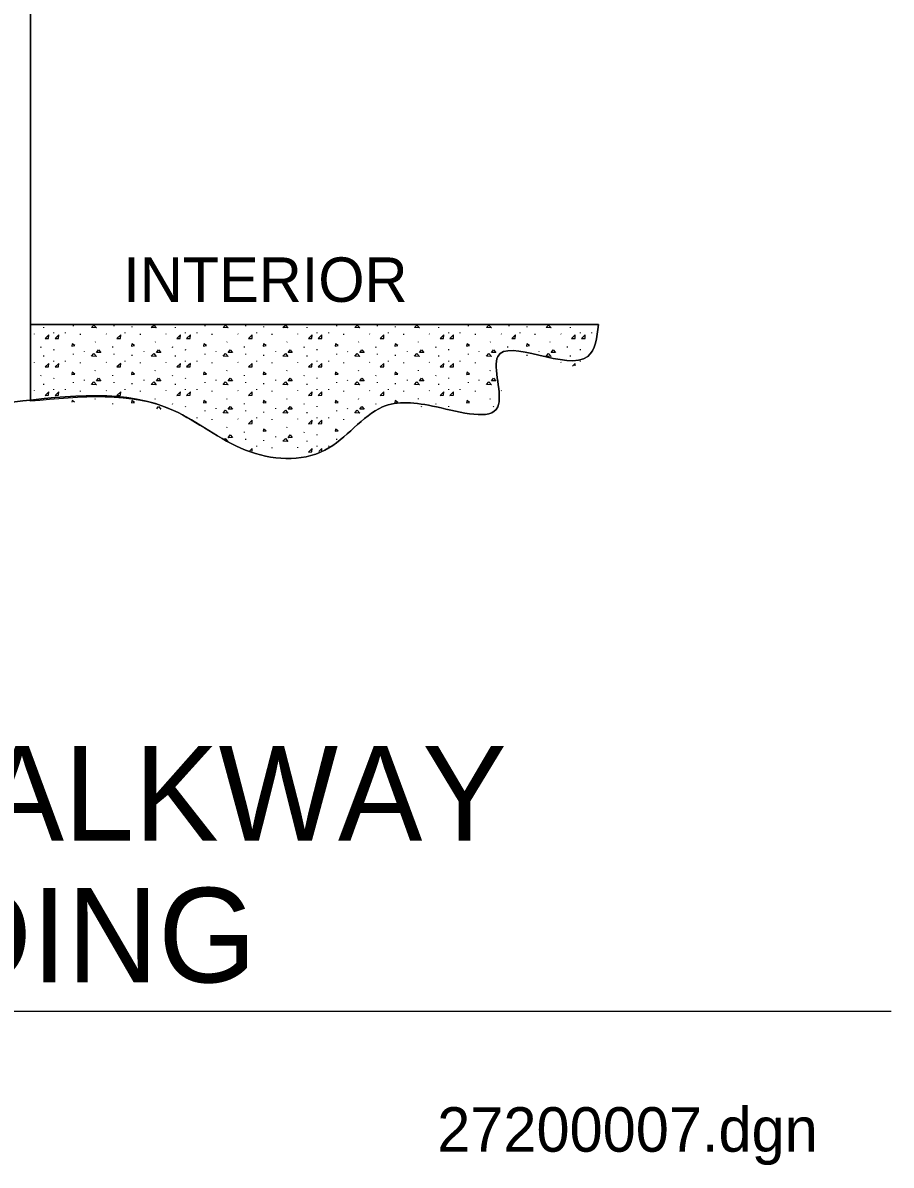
# Model space of a CAD drawing. Extents: x 10099.2 to 10148.4, y 10073.3 to 10116.7.
# Drawn here: x 10135.41 to 10148.42, y 10073.35 to 10090.47 of the extents above; entities that cross this region are included whole.
import ezdxf

# ---------------------------------------------------------------- set-up
doc = ezdxf.new("R2010")
doc.units = 0
for name, color, linetype in [('Level 52', 7, 'Continuous'), ('Level 60', 7, 'Continuous'), ('Level 61', 7, 'Continuous'), ('Level 63', 7, 'Continuous')]:
    doc.layers.add(name, color=color, linetype=linetype)

msp = doc.modelspace()

# ---------------------------------------------------------------- linework, layer by layer
at = {"layer": 'Level 52'}
msp.add_line((10099.233, 10075.654), (10148.423, 10075.654), dxfattribs=at)
at = {"layer": 'Level 60'}
for p, q in [((10144.04, 10085.947), (10135.528, 10085.947)), ((10135.528, 10085.947), (10144.04, 10085.947)), ((10135.528, 10085.947), (10144.04, 10085.947)), ((10135.591, 10085.8), (10135.588, 10085.808)), ((10135.729, 10085.894), (10135.729, 10085.906)), ((10135.879, 10085.818), (10135.879, 10085.828)), ((10136.052, 10085.818), (10136.052, 10085.828)), ((10136.175, 10085.921), (10136.175, 10085.932)), ((10136.28, 10085.792), (10136.28, 10085.804)), ((10136.667, 10085.8), (10136.664, 10085.808)), ((10136.782, 10085.921), (10136.782, 10085.932)), ((10136.949, 10085.818), (10136.949, 10085.828)), ((10137.052, 10085.904), (10137.052, 10085.915)), ((10137.176, 10085.792), (10137.176, 10085.804)), ((10137.563, 10085.8), (10137.56, 10085.808)), ((10137.701, 10085.894), (10137.701, 10085.906)), ((10137.851, 10085.818), (10137.851, 10085.828)), ((10138.024, 10085.818), (10138.024, 10085.828)), ((10138.147, 10085.921), (10138.147, 10085.932)), ((10138.252, 10085.792), (10138.252, 10085.804)), ((10138.639, 10085.8), (10138.636, 10085.808)), ((10138.754, 10085.921), (10138.754, 10085.932)), ((10138.921, 10085.818), (10138.921, 10085.828)), ((10139.024, 10085.904), (10139.024, 10085.915)), ((10139.148, 10085.792), (10139.148, 10085.804)), ((10139.535, 10085.8), (10139.532, 10085.808)), ((10139.673, 10085.894), (10139.673, 10085.906)), ((10139.823, 10085.818), (10139.823, 10085.828)), ((10139.996, 10085.818), (10139.996, 10085.828)), ((10140.119, 10085.921), (10140.119, 10085.932)), ((10140.224, 10085.792), (10140.224, 10085.804)), ((10140.611, 10085.8), (10140.608, 10085.808)), ((10140.726, 10085.921), (10140.726, 10085.932)), ((10140.893, 10085.818), (10140.893, 10085.828)), ((10140.996, 10085.904), (10140.996, 10085.915)), ((10141.12, 10085.792), (10141.12, 10085.804)), ((10141.507, 10085.8), (10141.504, 10085.808)), ((10141.645, 10085.894), (10141.645, 10085.906)), ((10141.795, 10085.818), (10141.795, 10085.828)), ((10141.968, 10085.818), (10141.968, 10085.828)), ((10142.091, 10085.921), (10142.091, 10085.932)), ((10142.196, 10085.792), (10142.196, 10085.804)), ((10142.583, 10085.8), (10142.58, 10085.808)), ((10142.698, 10085.921), (10142.698, 10085.932)), ((10142.865, 10085.818), (10142.865, 10085.828)), ((10142.968, 10085.904), (10142.968, 10085.915)), ((10143.092, 10085.792), (10143.092, 10085.804)), ((10143.479, 10085.8), (10143.476, 10085.808)), ((10143.617, 10085.894), (10143.617, 10085.906)), ((10143.767, 10085.818), (10143.767, 10085.828)), ((10143.94, 10085.818), (10143.94, 10085.828)), ((10135.686, 10085.603), (10135.688, 10085.614)), ((10136.5, 10085.679), (10136.504, 10085.688)), ((10136.761, 10085.603), (10136.764, 10085.614)), ((10137.396, 10085.679), (10137.4, 10085.688)), ((10137.658, 10085.603), (10137.66, 10085.614)), ((10138.472, 10085.679), (10138.476, 10085.688)), ((10138.733, 10085.603), (10138.736, 10085.614)), ((10139.368, 10085.679), (10139.372, 10085.688)), ((10139.63, 10085.603), (10139.632, 10085.614)), ((10140.444, 10085.679), (10140.448, 10085.688)), ((10140.705, 10085.603), (10140.708, 10085.614)), ((10141.34, 10085.679), (10141.344, 10085.688)), ((10141.602, 10085.603), (10141.604, 10085.614)), ((10142.416, 10085.679), (10142.42, 10085.688)), ((10142.678, 10085.603), (10142.68, 10085.614)), ((10143.312, 10085.679), (10143.316, 10085.688)), ((10143.574, 10085.603), (10143.576, 10085.614)), ((10135.729, 10085.469), (10135.729, 10085.481)), ((10135.879, 10085.563), (10135.882, 10085.575)), ((10136.175, 10085.496), (10136.175, 10085.507)), ((10136.336, 10085.534), (10136.337, 10085.543)), ((10136.782, 10085.496), (10136.782, 10085.507)), ((10137.052, 10085.479), (10137.052, 10085.49)), ((10137.233, 10085.534), (10137.233, 10085.543)), ((10137.701, 10085.469), (10137.701, 10085.481)), ((10137.851, 10085.563), (10137.854, 10085.575)), ((10138.147, 10085.496), (10138.147, 10085.507)), ((10138.308, 10085.534), (10138.309, 10085.543)), ((10138.754, 10085.496), (10138.754, 10085.507)), ((10139.024, 10085.479), (10139.024, 10085.49)), ((10139.205, 10085.534), (10139.205, 10085.543)), ((10139.673, 10085.469), (10139.673, 10085.481)), ((10139.823, 10085.563), (10139.826, 10085.575)), ((10140.119, 10085.496), (10140.119, 10085.507)), ((10140.28, 10085.534), (10140.281, 10085.543)), ((10140.726, 10085.496), (10140.726, 10085.507)), ((10140.996, 10085.479), (10140.996, 10085.49)), ((10141.177, 10085.534), (10141.177, 10085.543)), ((10141.645, 10085.469), (10141.645, 10085.481)), ((10141.795, 10085.563), (10141.798, 10085.575)), ((10142.091, 10085.496), (10142.091, 10085.507)), ((10142.252, 10085.534), (10142.253, 10085.543)), ((10142.968, 10085.479), (10142.968, 10085.49)), ((10143.149, 10085.534), (10143.149, 10085.543)), ((10143.617, 10085.469), (10143.617, 10085.481)), ((10143.767, 10085.563), (10143.77, 10085.575)), ((10135.591, 10085.375), (10135.588, 10085.383)), ((10135.879, 10085.392), (10135.879, 10085.402)), ((10136.052, 10085.392), (10136.052, 10085.402)), ((10136.28, 10085.367), (10136.28, 10085.378)), ((10136.5, 10085.254), (10136.504, 10085.263)), ((10136.667, 10085.375), (10136.664, 10085.383)), ((10136.949, 10085.392), (10136.949, 10085.402)), ((10137.176, 10085.367), (10137.176, 10085.378)), ((10137.396, 10085.254), (10137.4, 10085.263)), ((10137.563, 10085.375), (10137.56, 10085.383)), ((10137.851, 10085.392), (10137.851, 10085.402)), ((10138.024, 10085.392), (10138.024, 10085.402)), ((10138.252, 10085.367), (10138.252, 10085.378)), ((10138.472, 10085.254), (10138.476, 10085.263)), ((10138.639, 10085.375), (10138.636, 10085.383)), ((10138.921, 10085.392), (10138.921, 10085.402)), ((10139.148, 10085.367), (10139.148, 10085.378)), ((10139.368, 10085.254), (10139.372, 10085.263)), ((10139.535, 10085.375), (10139.532, 10085.383)), ((10139.823, 10085.392), (10139.823, 10085.402)), ((10139.996, 10085.392), (10139.996, 10085.402)), ((10140.224, 10085.367), (10140.224, 10085.378)), ((10140.444, 10085.254), (10140.448, 10085.263)), ((10140.611, 10085.375), (10140.608, 10085.383)), ((10140.893, 10085.392), (10140.893, 10085.402)), ((10141.12, 10085.367), (10141.12, 10085.378)), ((10141.34, 10085.254), (10141.344, 10085.263)), ((10141.507, 10085.375), (10141.504, 10085.383)), ((10141.795, 10085.392), (10141.795, 10085.402)), ((10141.968, 10085.392), (10141.968, 10085.402)), ((10142.196, 10085.367), (10142.196, 10085.378)), ((10142.416, 10085.254), (10142.42, 10085.263)), ((10143.479, 10085.375), (10143.476, 10085.383)), ((10143.767, 10085.392), (10143.767, 10085.402)), ((10135.686, 10085.177), (10135.688, 10085.189)), ((10135.879, 10085.138), (10135.882, 10085.149)), ((10136.175, 10085.07), (10136.175, 10085.082)), ((10136.336, 10085.109), (10136.337, 10085.118)), ((10136.761, 10085.177), (10136.764, 10085.189)), ((10136.782, 10085.07), (10136.782, 10085.082)), ((10137.233, 10085.109), (10137.233, 10085.118)), ((10137.658, 10085.177), (10137.66, 10085.189)), ((10137.851, 10085.138), (10137.854, 10085.149)), ((10138.147, 10085.07), (10138.147, 10085.082)), ((10138.308, 10085.109), (10138.309, 10085.118)), ((10138.733, 10085.177), (10138.736, 10085.189)), ((10138.754, 10085.07), (10138.754, 10085.082)), ((10139.205, 10085.109), (10139.205, 10085.118)), ((10139.63, 10085.177), (10139.632, 10085.189)), ((10139.823, 10085.138), (10139.826, 10085.149)), ((10140.119, 10085.07), (10140.119, 10085.082)), ((10140.28, 10085.109), (10140.281, 10085.118)), ((10140.705, 10085.177), (10140.708, 10085.189)), ((10140.726, 10085.07), (10140.726, 10085.082)), ((10141.177, 10085.109), (10141.177, 10085.118)), ((10141.602, 10085.177), (10141.604, 10085.189)), ((10141.795, 10085.138), (10141.798, 10085.149)), ((10142.091, 10085.07), (10142.091, 10085.082)), ((10142.252, 10085.109), (10142.253, 10085.118)), ((10135.591, 10084.95), (10135.588, 10084.958)), ((10135.729, 10085.044), (10135.729, 10085.055)), ((10135.879, 10084.967), (10135.879, 10084.977)), ((10136.052, 10084.967), (10136.052, 10084.977)), ((10136.28, 10084.942), (10136.28, 10084.953)), ((10136.667, 10084.95), (10136.664, 10084.958)), ((10136.949, 10084.967), (10136.949, 10084.977)), ((10137.052, 10085.053), (10137.052, 10085.065)), ((10137.176, 10084.942), (10137.176, 10084.953)), ((10137.563, 10084.95), (10137.56, 10084.958)), ((10137.701, 10085.044), (10137.701, 10085.055)), ((10137.851, 10084.967), (10137.851, 10084.977)), ((10138.024, 10084.967), (10138.024, 10084.977)), ((10138.252, 10084.942), (10138.252, 10084.953)), ((10138.639, 10084.95), (10138.636, 10084.958)), ((10138.921, 10084.967), (10138.921, 10084.977)), ((10139.024, 10085.053), (10139.024, 10085.065)), ((10139.148, 10084.942), (10139.148, 10084.953)), ((10139.535, 10084.95), (10139.532, 10084.958)), ((10139.673, 10085.044), (10139.673, 10085.055)), ((10139.823, 10084.967), (10139.823, 10084.977)), ((10139.996, 10084.967), (10139.996, 10084.977)), ((10140.224, 10084.942), (10140.224, 10084.953)), ((10140.611, 10084.95), (10140.608, 10084.958)), ((10140.893, 10084.967), (10140.893, 10084.977)), ((10140.996, 10085.053), (10140.996, 10085.065)), ((10141.12, 10084.942), (10141.12, 10084.953)), ((10141.507, 10084.95), (10141.504, 10084.958)), ((10141.645, 10085.044), (10141.645, 10085.055)), ((10141.795, 10084.967), (10141.795, 10084.977)), ((10141.968, 10084.967), (10141.968, 10084.977)), ((10142.196, 10084.942), (10142.196, 10084.953)), ((10142.583, 10084.95), (10142.58, 10084.958)), ((10136.5, 10084.828), (10136.504, 10084.837)), ((10136.761, 10084.752), (10136.764, 10084.764)), ((10137.396, 10084.828), (10137.4, 10084.837)), ((10137.658, 10084.752), (10137.66, 10084.764)), ((10138.472, 10084.828), (10138.476, 10084.837)), ((10138.733, 10084.752), (10138.736, 10084.764)), ((10139.368, 10084.828), (10139.372, 10084.837)), ((10139.63, 10084.752), (10139.632, 10084.764)), ((10140.444, 10084.828), (10140.448, 10084.837)), ((10140.705, 10084.752), (10140.708, 10084.764)), ((10141.34, 10084.828), (10141.344, 10084.837)), ((10141.602, 10084.752), (10141.604, 10084.764)), ((10142.416, 10084.828), (10142.42, 10084.837)), ((10137.851, 10084.713), (10137.854, 10084.724)), ((10138.147, 10084.645), (10138.147, 10084.657)), ((10138.308, 10084.684), (10138.309, 10084.693)), ((10138.754, 10084.645), (10138.754, 10084.657)), ((10139.024, 10084.628), (10139.024, 10084.639)), ((10139.205, 10084.684), (10139.205, 10084.693)), ((10139.673, 10084.618), (10139.673, 10084.63)), ((10139.823, 10084.713), (10139.826, 10084.724)), ((10140.119, 10084.645), (10140.119, 10084.657)), ((10140.28, 10084.684), (10140.281, 10084.693)), ((10141.795, 10084.713), (10141.798, 10084.724)), ((10138.024, 10084.542), (10138.024, 10084.552)), ((10138.252, 10084.516), (10138.252, 10084.528)), ((10138.472, 10084.403), (10138.476, 10084.412)), ((10138.639, 10084.525), (10138.636, 10084.533)), ((10138.921, 10084.542), (10138.921, 10084.552)), ((10139.148, 10084.516), (10139.148, 10084.528)), ((10139.368, 10084.403), (10139.372, 10084.412)), ((10139.535, 10084.525), (10139.532, 10084.533)), ((10139.823, 10084.542), (10139.823, 10084.552)), ((10139.996, 10084.542), (10139.996, 10084.552)), ((10140.224, 10084.516), (10140.224, 10084.528)), ((10138.733, 10084.327), (10138.736, 10084.339)), ((10138.754, 10084.22), (10138.754, 10084.231)), ((10139.205, 10084.258), (10139.205, 10084.267)), ((10139.63, 10084.327), (10139.632, 10084.339)), ((10139.823, 10084.287), (10139.826, 10084.299)), ((10140.119, 10084.22), (10140.119, 10084.231)), ((10138.921, 10084.117), (10138.921, 10084.127)), ((10139.024, 10084.203), (10139.024, 10084.214)), ((10139.148, 10084.091), (10139.148, 10084.103)), ((10139.535, 10084.099), (10139.532, 10084.107)), ((10139.673, 10084.193), (10139.673, 10084.205)), ((10139.823, 10084.117), (10139.823, 10084.127)), ((10139.996, 10084.117), (10139.996, 10084.127))]:
    msp.add_line(p, q, dxfattribs=at)
for points in [[(10136.443, 10085.899), (10136.478, 10085.937), (10136.518, 10085.894)], [(10137.338, 10085.899), (10137.375, 10085.937), (10137.414, 10085.894)], [(10138.415, 10085.899), (10138.45, 10085.937), (10138.49, 10085.894)], [(10139.31, 10085.899), (10139.347, 10085.937), (10139.386, 10085.894)], [(10140.387, 10085.899), (10140.422, 10085.937), (10140.462, 10085.894)], [(10141.282, 10085.899), (10141.319, 10085.937), (10141.358, 10085.894)], [(10142.359, 10085.899), (10142.394, 10085.937), (10142.434, 10085.894)], [(10143.254, 10085.899), (10143.291, 10085.937), (10143.33, 10085.894)], [(10135.801, 10085.738), (10135.803, 10085.789), (10135.748, 10085.735)], [(10135.949, 10085.738), (10135.952, 10085.789), (10135.896, 10085.735)], [(10136.876, 10085.738), (10136.88, 10085.789), (10136.824, 10085.735)], [(10137.773, 10085.738), (10137.775, 10085.789), (10137.72, 10085.735)], [(10137.921, 10085.738), (10137.924, 10085.789), (10137.868, 10085.735)], [(10138.848, 10085.738), (10138.852, 10085.789), (10138.796, 10085.735)], [(10139.745, 10085.738), (10139.747, 10085.789), (10139.692, 10085.735)], [(10139.893, 10085.738), (10139.896, 10085.789), (10139.84, 10085.735)], [(10140.82, 10085.738), (10140.824, 10085.789), (10140.768, 10085.735)], [(10141.717, 10085.738), (10141.719, 10085.789), (10141.664, 10085.735)], [(10141.865, 10085.738), (10141.868, 10085.789), (10141.813, 10085.735)], [(10142.792, 10085.738), (10142.796, 10085.789), (10142.74, 10085.735)], [(10143.689, 10085.738), (10143.691, 10085.789), (10143.636, 10085.735)], [(10143.838, 10085.738), (10143.84, 10085.789), (10143.785, 10085.735)], [(10136.147, 10085.623), (10136.192, 10085.629), (10136.153, 10085.655)], [(10137.042, 10085.623), (10137.087, 10085.629), (10137.049, 10085.655)], [(10138.119, 10085.623), (10138.164, 10085.629), (10138.125, 10085.655)], [(10139.014, 10085.623), (10139.059, 10085.629), (10139.021, 10085.655)], [(10140.091, 10085.623), (10140.136, 10085.629), (10140.097, 10085.655)], [(10140.986, 10085.623), (10141.032, 10085.629), (10140.993, 10085.655)], [(10142.063, 10085.623), (10142.108, 10085.629), (10142.069, 10085.655)], [(10142.958, 10085.623), (10143.004, 10085.629), (10142.965, 10085.655)], [(10136.443, 10085.473), (10136.478, 10085.511), (10136.518, 10085.469)], [(10136.519, 10085.526), (10136.548, 10085.567), (10136.584, 10085.528)], [(10137.338, 10085.473), (10137.375, 10085.511), (10137.414, 10085.469)], [(10137.415, 10085.526), (10137.445, 10085.567), (10137.479, 10085.528)], [(10138.415, 10085.473), (10138.45, 10085.511), (10138.49, 10085.469)], [(10138.491, 10085.526), (10138.52, 10085.567), (10138.556, 10085.528)], [(10139.31, 10085.473), (10139.347, 10085.511), (10139.386, 10085.469)], [(10139.387, 10085.526), (10139.417, 10085.567), (10139.451, 10085.528)], [(10140.387, 10085.473), (10140.422, 10085.511), (10140.462, 10085.469)], [(10140.463, 10085.526), (10140.492, 10085.567), (10140.528, 10085.528)], [(10141.282, 10085.473), (10141.319, 10085.511), (10141.358, 10085.469)], [(10141.359, 10085.526), (10141.389, 10085.567), (10141.423, 10085.528)], [(10142.359, 10085.473), (10142.394, 10085.511), (10142.434, 10085.469)], [(10142.435, 10085.526), (10142.464, 10085.567), (10142.5, 10085.528)], [(10143.254, 10085.473), (10143.291, 10085.511), (10143.33, 10085.469)], [(10143.331, 10085.526), (10143.361, 10085.567), (10143.395, 10085.528)], [(10135.801, 10085.313), (10135.803, 10085.364), (10135.748, 10085.31)], [(10135.949, 10085.313), (10135.952, 10085.364), (10135.896, 10085.31)], [(10136.876, 10085.313), (10136.88, 10085.364), (10136.824, 10085.31)], [(10137.773, 10085.313), (10137.775, 10085.364), (10137.72, 10085.31)], [(10137.921, 10085.313), (10137.924, 10085.364), (10137.868, 10085.31)], [(10138.848, 10085.313), (10138.852, 10085.364), (10138.796, 10085.31)], [(10139.745, 10085.313), (10139.747, 10085.364), (10139.692, 10085.31)], [(10139.893, 10085.313), (10139.896, 10085.364), (10139.84, 10085.31)], [(10140.82, 10085.313), (10140.824, 10085.364), (10140.768, 10085.31)], [(10141.717, 10085.313), (10141.719, 10085.364), (10141.664, 10085.31)], [(10141.865, 10085.313), (10141.868, 10085.364), (10141.813, 10085.31)], [(10136.147, 10085.198), (10136.192, 10085.204), (10136.153, 10085.23)], [(10136.443, 10085.048), (10136.478, 10085.086), (10136.518, 10085.043)], [(10136.519, 10085.101), (10136.548, 10085.141), (10136.584, 10085.103)], [(10137.042, 10085.198), (10137.087, 10085.204), (10137.049, 10085.23)], [(10137.338, 10085.048), (10137.375, 10085.086), (10137.414, 10085.043)], [(10137.415, 10085.101), (10137.445, 10085.141), (10137.479, 10085.103)], [(10138.119, 10085.198), (10138.164, 10085.204), (10138.125, 10085.23)], [(10138.415, 10085.048), (10138.45, 10085.086), (10138.49, 10085.043)], [(10138.491, 10085.101), (10138.52, 10085.141), (10138.556, 10085.103)], [(10139.014, 10085.198), (10139.059, 10085.204), (10139.021, 10085.23)], [(10139.31, 10085.048), (10139.347, 10085.086), (10139.386, 10085.043)], [(10139.387, 10085.101), (10139.417, 10085.141), (10139.451, 10085.103)], [(10140.091, 10085.198), (10140.136, 10085.204), (10140.097, 10085.23)], [(10140.387, 10085.048), (10140.422, 10085.086), (10140.462, 10085.043)], [(10140.463, 10085.101), (10140.492, 10085.141), (10140.528, 10085.103)], [(10140.986, 10085.198), (10141.032, 10085.204), (10140.993, 10085.23)], [(10141.282, 10085.048), (10141.319, 10085.086), (10141.358, 10085.043)], [(10141.359, 10085.101), (10141.389, 10085.141), (10141.423, 10085.103)], [(10142.063, 10085.198), (10142.108, 10085.204), (10142.069, 10085.23)], [(10142.359, 10085.048), (10142.394, 10085.086), (10142.434, 10085.043)], [(10142.435, 10085.101), (10142.464, 10085.141), (10142.5, 10085.103)], [(10135.801, 10084.888), (10135.803, 10084.939), (10135.748, 10084.884)], [(10135.949, 10084.888), (10135.952, 10084.939), (10135.896, 10084.884)], [(10136.876, 10084.888), (10136.88, 10084.939), (10136.824, 10084.884)], [(10137.773, 10084.888), (10137.775, 10084.939), (10137.72, 10084.884)], [(10137.921, 10084.888), (10137.924, 10084.939), (10137.868, 10084.884)], [(10138.848, 10084.888), (10138.852, 10084.939), (10138.796, 10084.884)], [(10139.745, 10084.888), (10139.747, 10084.939), (10139.692, 10084.884)], [(10139.893, 10084.888), (10139.896, 10084.939), (10139.84, 10084.884)], [(10140.82, 10084.888), (10140.824, 10084.939), (10140.768, 10084.884)], [(10141.717, 10084.888), (10141.719, 10084.939), (10141.664, 10084.884)], [(10141.865, 10084.888), (10141.868, 10084.939), (10141.813, 10084.884)], [(10137.042, 10084.773), (10137.087, 10084.779), (10137.049, 10084.805)], [(10138.119, 10084.773), (10138.164, 10084.779), (10138.125, 10084.805)], [(10139.014, 10084.773), (10139.059, 10084.779), (10139.021, 10084.805)], [(10140.091, 10084.773), (10140.136, 10084.779), (10140.097, 10084.805)], [(10140.986, 10084.773), (10141.032, 10084.779), (10140.993, 10084.805)], [(10142.063, 10084.773), (10142.108, 10084.779), (10142.069, 10084.805)], [(10138.415, 10084.623), (10138.45, 10084.661), (10138.49, 10084.618)], [(10138.491, 10084.675), (10138.52, 10084.716), (10138.556, 10084.677)], [(10139.31, 10084.623), (10139.347, 10084.661), (10139.386, 10084.618)], [(10139.387, 10084.675), (10139.417, 10084.716), (10139.451, 10084.677)], [(10140.387, 10084.623), (10140.422, 10084.661), (10140.462, 10084.618)], [(10140.463, 10084.675), (10140.492, 10084.716), (10140.528, 10084.677)], [(10138.848, 10084.462), (10138.852, 10084.513), (10138.796, 10084.459)], [(10139.745, 10084.462), (10139.747, 10084.513), (10139.692, 10084.459)], [(10139.893, 10084.462), (10139.896, 10084.513), (10139.84, 10084.459)], [(10138.491, 10084.25), (10138.52, 10084.291), (10138.556, 10084.252)], [(10139.014, 10084.348), (10139.059, 10084.353), (10139.021, 10084.379)], [(10139.31, 10084.198), (10139.347, 10084.236), (10139.386, 10084.193)], [(10139.387, 10084.25), (10139.417, 10084.291), (10139.451, 10084.252)], [(10140.091, 10084.348), (10140.136, 10084.353), (10140.097, 10084.379)], [(10139.745, 10084.037), (10139.747, 10084.088), (10139.692, 10084.034)]]:
    msp.add_lwpolyline(points, close=True, dxfattribs=at)
for points in [[(10143.69, 10085.325), (10143.691, 10085.364), (10143.647, 10085.321)], [(10136.188, 10084.782), (10136.153, 10084.805), (10136.148, 10084.782)], [(10137.42, 10084.683), (10137.445, 10084.716), (10137.479, 10084.677), (10137.473, 10084.677)], [(10141.385, 10084.711), (10141.389, 10084.716), (10141.394, 10084.711)], [(10142.46, 10084.711), (10142.464, 10084.716), (10142.469, 10084.711)], [(10138.44, 10084.225), (10138.45, 10084.236), (10138.49, 10084.193), (10138.488, 10084.193)], [(10138.849, 10084.046), (10138.852, 10084.088), (10138.814, 10084.052)], [(10139.894, 10084.053), (10139.896, 10084.088), (10139.851, 10084.044)]]:
    msp.add_lwpolyline(points, dxfattribs=at)
for points in [[(10135.253, 10084.782), (10137.673, 10084.657), (10138.752, 10084.063), (10139.939, 10084.063), (10140.802, 10084.711), (10141.611, 10084.711), (10142.529, 10084.711), (10142.529, 10085.466), (10143.878, 10085.466), (10144.04, 10085.947)], [(10144.04, 10085.947), (10143.878, 10085.466), (10142.529, 10085.466), (10142.529, 10084.711), (10141.611, 10084.711), (10140.802, 10084.711), (10139.939, 10084.063), (10138.752, 10084.063), (10137.673, 10084.657), (10135.528, 10084.796)], [(10144.04, 10085.947), (10143.878, 10085.466), (10142.529, 10085.466), (10142.529, 10084.711), (10141.611, 10084.711), (10140.802, 10084.711), (10139.939, 10084.063), (10138.752, 10084.063), (10137.673, 10084.657), (10135.528, 10084.796)]]:
    msp.add_spline(points, degree=3, dxfattribs=at)
at = {"layer": 'Level 61'}
for p, q in [((10135.528, 10116.255), (10135.528, 10084.796)), ((10135.528, 10084.796), (10135.528, 10116.255)), ((10135.528, 10116.255), (10135.528, 10085.947)), ((10135.528, 10084.796), (10135.528, 10112.125)), ((10135.528, 10085.947), (10144.04, 10085.947))]:
    msp.add_line(p, q, dxfattribs=at)
msp.add_spline([(10144.04, 10085.947), (10143.878, 10085.466), (10142.529, 10085.466), (10142.529, 10084.711), (10141.611, 10084.711), (10140.802, 10084.711), (10139.939, 10084.063), (10138.752, 10084.063), (10137.673, 10084.657), (10135.253, 10084.782)], degree=3, dxfattribs=at)

# ---------------------------------------------------------------- texts
at = {"layer": 'Level 52'}
for s, height, p in [('EMERGENCY TELEPHONE NEAR WALKWAY ', 1.41667, (10102.452, 10078.211)), ('SURFACE MOUNTED TO BUILDING', 1.41667, (10107.129, 10076.086)), ('27200007.dgn', 0.66667, (10141.622, 10073.548))]:
    msp.add_text(s, height=height, dxfattribs=at).set_placement(p)
at = {"layer": 'Level 63'}
msp.add_text('INTERIOR', height=0.6667, dxfattribs=at).set_placement((10136.918, 10086.285))

doc.saveas('drawing.dxf')
